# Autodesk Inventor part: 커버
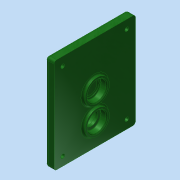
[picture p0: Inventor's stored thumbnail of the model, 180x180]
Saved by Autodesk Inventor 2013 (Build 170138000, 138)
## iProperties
Created: 2016-02
Part Number: 커버
Material: 알루미늄 6061
Document SubType Name: Modeling
Designer: mduedu
Density: 1 g/cm^3
Mass: 100.462 g
Surface Area: 266.629 cm^2
Volume: 100.462 cm^3
Author: mduedu
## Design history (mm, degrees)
sketch "스케치1"
  geometry: L1 (63, 47)-(-47, 47); L2 (-47, 47)-(-47, -47); L3 (-47, -47)-(63, -47); L4 (63, -47)-(63, 47); 2 further points
  constraints: 8 end point, 2 parallel, 1 horizontal, 1 horizontal alignment, 1 midpoint, 1 perpendicular
  dimensions: "d102" = 94 distance of L3.end L1.start; "d104" = 47 distance from line of L2 point (0, 0); "d105" = 110 distance of L1.start L1.end
extrude "돌출1" new body sketch "스케치1" distance "d1" = 10; taper "d2" = 0 deg
sketch "스케치2"
  geometry: C1 r 14 at (0, 11); 1 further point
  constraints: 1 centre point, 1 vertical alignment
  dimensions: "d3" = 28 diameter of C1; "d6" = 11 distance of C1.centre point (0, 0)
extrude "돌출2" join sketch "스케치2" distance "d7" = 3; taper "d8" = 0 deg
sketch "스케치3"
  geometry: C1 r 14 at (0, -20); 1 further point
  constraints: 1 centre point, 1 vertical alignment
  dimensions: "d9" = 28 diameter of C1; "d10" = 20 distance of C1.centre point (0, 0)
extrude "돌출3" join sketch "스케치3" distance "d11" = 3; taper "d12" = 0 deg
hole "구멍1" diameter "d15" = 22; stored, may be unused: countersink angle "d19" = 90 deg, drill point angle "d21" = 0 deg; dims "d13" = 10, "d14" = 10, "d16" = 6, "d17" = 4, "d18" = 2, "d20" = 7
hole "구멍2" diameter "d24" = 18; stored, may be unused: countersink angle "d28" = 90 deg, drill point angle "d30" = 0 deg; dims "d22" = 10, "d23" = 10, "d25" = 6, "d26" = 4, "d27" = 2, "d29" = 1
hole "구멍3" diameter "d33" = 22; stored, may be unused: countersink angle "d37" = 90 deg, drill point angle "d39" = 0 deg; dims "d34" = 6, "d35" = 4, "d36" = 2, "d38" = 7, "d73" = 10, "d74" = 10
sketch "스케치4"
  geometry: C1 r 14 at (0, -20) reference; C2 r 18 at (0, -20); 1 further point
  constraints: 1 centre point, 1 coincident
  dimensions: "d40" = 36 diameter of C2
extrude "돌출4" join sketch "스케치4" distance "d41" = 4; taper "d42" = 0 deg
hole "구멍4" diameter "d45" = 22; stored, may be unused: countersink angle "d49" = 90 deg, drill point angle "d51" = 0 deg; dims "d43" = 10, "d44" = 10, "d46" = 6, "d47" = 4, "d48" = 2, "d50" = 7
hole "구멍5" diameter "d54" = 15; stored, may be unused: countersink angle "d58" = 90 deg, drill point angle "d60" = 0 deg; dims "d52" = 10, "d53" = 10, "d55" = 6, "d56" = 4, "d57" = 2, "d59" = 7
fillet "모깎기1" dims "d61" = 0.3
fillet "모깎기2" dims "d62" = 2
chamfer "모따기1" distance "d63" = 1; stored, may be unused: second distance "d64" = 2, angle "d65" = 45 deg
fillet "모깎기6" dims "d88" = 2
fillet "모깎기4" dims "d75" = 2
sketch "스케치9"
  geometry: L1 (47, 63)-(47, -47) reference; L2 (-47, 63)-(47, 63) reference; L3 (-47, -47)-(-47, 63) reference; L4 (47, -47)-(-47, -47) reference; L5 (37, 53)-(37, -37); L6 (37, -37)-(-37, -37); L7 (-37, -37)-(-37, 53); L8 (-37, 53)-(37, 53); C1 r 20 at (0, -20) reference; 5 further points
  constraints: 8 end point, 4 coincident, 3 other
  dimensions: "d107" = 10 distance between parallel lines of L8 L2
hole "구멍7" sketch "스케치9" at (-37, 53), (37, 53), (37, -37), (-37, -37) diameter "d108" = 4.5; stored, may be unused: countersink angle "d112" = 90 deg, drill point angle "d114" = 118 deg; dims "d109" = 6, "d110" = 8, "d111" = 4.6, "d113" = 8
fillet "모깎기8" dims "d106" = 3
fillet "모깎기9" dims "d115" = 3
node "솔리드1"
node "투영된 루프2"
